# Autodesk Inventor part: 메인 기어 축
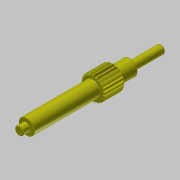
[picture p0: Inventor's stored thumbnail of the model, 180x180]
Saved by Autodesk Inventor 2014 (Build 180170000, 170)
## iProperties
Created: 2018-12
Part Number: 메인 기어 축
Material: 강철, 연강
Document SubType Name: Modeling
Designer: mduedu
Categories: <?xml version="1.0" encoding="UTF-16"?> <MemberInstance><Categories><FamilyTemplate><FamilyTemplateParameter ValueType="xs:double" Id="1" ObjectReferenceKey="da
Density: 7.86 g/cm^3
Appearance: Yellow
Mass: 179.676 g
Surface Area: 75.4119 cm^2
Volume: 22.8595 cm^3
CustomPartVersion: 1
Author: mduedu
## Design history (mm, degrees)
sketch "Sketch1"
  geometry: C1 r 11.3 at (0, 0)
  constraints: 1 centre point
  dimensions: "d0" = 22.6 diameter of C1 (= da_da)
extrude "Extrusion1" new body sketch "Sketch1" distance "d1" = 20 (= da_b); taper "d2" = 0 deg
workplane "Work Plane2"
sketch "Sketch2"
  geometry: C1 r 11.3 at (0, 0) reference; C2 r 10.5 at (0, 0)
  constraints: 1 centre point, 1 coincident
  dimensions: "d3" = 21 diameter of C2 (= da_dw)
feature "피치 지름" sketch "Sketch2" dims "d4" = 10, "d5" = 0
workplane "Work Plane8"
workplane "Work Plane9"
chamfer "모따기1" distance "d49" = 1; stored, may be unused: second distance "d50" = 2, angle "d51" = 45 deg
sketch "스케치3"
  geometry: C1 r 7.5 at (0, 0); 1 further point
  constraints: 1 centre point, 1 coincident
  dimensions: "d52" = 15 diameter of C1
extrude "돌출2" join sketch "스케치3" distance "d53" = 64; taper "d54" = 0 deg
sketch "스케치4"
  geometry: C1 r 4 at (0, 0); 1 further point
  constraints: 1 centre point, 1 coincident
  dimensions: "d55" = 8 diameter of C1
extrude "돌출3" join sketch "스케치4" distance "d56" = 7; taper "d57" = 0 deg
sketch "스케치5"
  geometry: C1 r 7.5 at (0, 0) reference; C2 r 7.5 at (0, 0) reference; 1 further point
extrude "돌출4" join sketch "스케치5" distance "d58" = 16; taper "d59" = 0 deg
sketch "스케치6"
  geometry: C1 r 4 at (0, 0); 1 further point
  constraints: 1 centre point, 1 coincident
  dimensions: "d60" = 8 diameter of C1
extrude "돌출5" join sketch "스케치6" distance "d61" = 30; taper "d62" = 0 deg
chamfer "모따기2" distance "d63" = 0.5; stored, may be unused: second distance "d64" = 2, angle "d65" = 45 deg
fillet "모깎기1" dims "d66" = 0.5
feature "스퍼 기어" dims "da_b" = 20, "da_d" = 21, "da_aw" = 31, "da_da" = 22.6, "da_df" = 19.086, "da_dw" = 21, angle "da_beta" = 0 deg, "da_lefttooth" = 0, "da_righttooth" = 0
sketch "스케치7" dims "d67" = 18
  geometry: C1 r 0.25 at (0, -9); 2 further points
  constraints: 2 vertical alignment, 1 centre point, 1 coincident, 2 other
  dimensions: "d68" = 0.5 diameter of C1
extrude "돌출6" join sketch "스케치7" distance "d69" = 0.3; taper "d70" = 0 deg
body "Solid1"
body "Srf1"
node "투영된 루프1"
other parameters: "d16" = 31 (= da_aw), "d17" = 0, "d34" = 1.496 (computed from da_z), "d39" = 0, "d41" = 0, "d43" = 31 (= da_aw), "d46" = 31 (= da_aw), "d47" = 0, "d48" = 0
